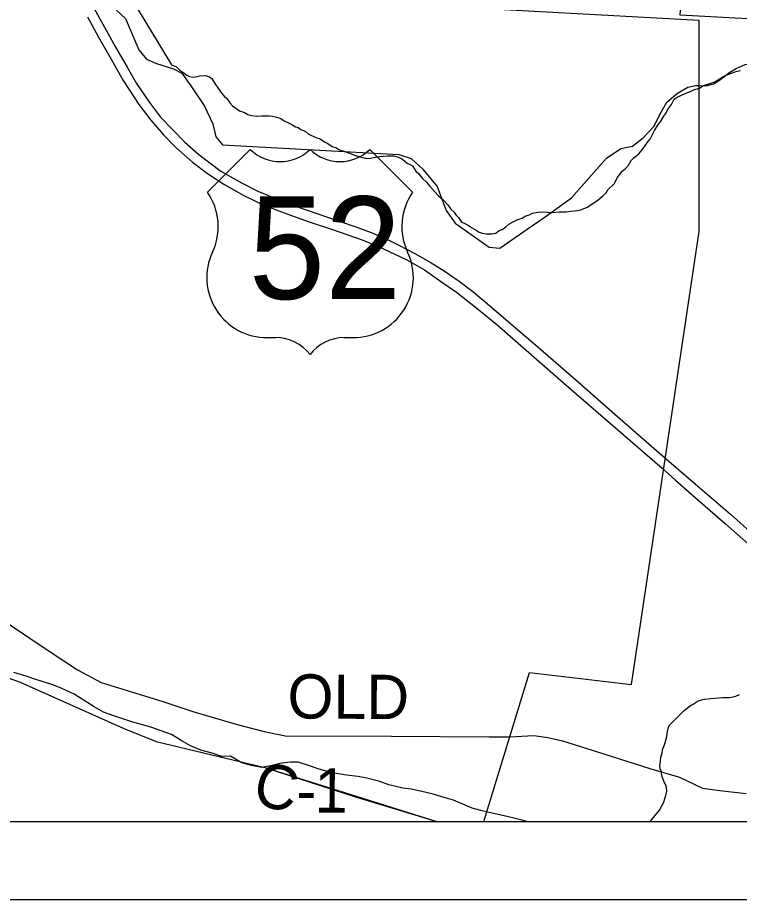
# Model space of a CAD drawing. Extents: x 0 to 45.4, y -2.2 to 22.
# Drawn here: x 5.063 to 5.991, y 14 to 15.133 of the extents above; entities that cross this region are included whole.
import ezdxf

# ---------------------------------------------------------------- set-up
doc = ezdxf.new("R2010")
doc.units = 0
for name, color, linetype in [('GM_X_Corporation', 7, 'Continuous'), ('GM_X_County_Road', 7, 'Continuous'), ('GM_X_County_Road_Text', 7, 'Continuous'), ('GM_X_Major_River', 7, 'Continuous'), ('GM_X_Minor_River', 7, 'Continuous'), ('GM_X_Township_Road', 7, 'Continuous'), ('GM_X_US_Location', 7, 'Continuous'), ('GM_X_US_Route', 7, 'Continuous'), ('GM_X_US_Shield', 7, 'Continuous'), ('SH_Data', 7, 'Continuous')]:
    doc.layers.add(name, color=color, linetype=linetype)

msp = doc.modelspace()

# ---------------------------------------------------------------- linework, layer by layer
at = {"layer": 'GM_X_Corporation'}
msp.add_lwpolyline([(5.9818, 16.1569), (7.1036, 16.0876), (7.0412, 15.0748), (5.9148, 15.1362)], close=True, dxfattribs=at)
for points in [[(3.8978, 15.2272), (3.9542, 15.1285), (4.0477, 14.9842), (4.1352, 14.8715), (4.2196, 14.8002), (4.388, 14.6465), (4.4527, 14.6021), (4.5557, 14.522), (4.7063, 14.4272), (4.7879, 14.3851), (4.9751, 14.3119), (5.0667, 14.2789), (5.1988, 14.2201), (5.2415, 14.2027), (5.3809, 14.1693), (5.499, 14.1314), (5.6021, 14.1), (7.0413, 14.1)], [(3.8978, 15.2272), (3.9542, 15.1285), (4.0477, 14.9842), (4.1352, 14.8715), (4.2196, 14.8002), (4.388, 14.6465), (4.4527, 14.6021), (4.5557, 14.522), (4.7063, 14.4272), (4.9751, 14.3119), (5.0667, 14.2789), (5.1988, 14.2201), (5.2415, 14.2027), (5.3809, 14.1693), (5.6023, 14.1), (5.6624, 14.1), (5.7213, 14.2916), (5.8523, 14.276), (5.9392, 14.8581), (5.9392, 15.1293), (5.6491, 15.1452)], [(4.8407, 15.1929), (4.8223, 15.0904), (4.8187, 15.0253), (4.8105, 14.8879), (4.809, 14.8625), (4.8057, 14.8075), (4.7972, 14.536), (4.7879, 14.3851), (4.9751, 14.3119), (5.0667, 14.2789), (5.1988, 14.2201), (5.2415, 14.2027), (5.3809, 14.1693), (5.499, 14.1314), (5.6021, 14.1), (7.0413, 14.1)]]:
    msp.add_lwpolyline(points, dxfattribs=at)
at = {"layer": 'GM_X_County_Road'}
for points in [[(5.0206, 14.3757), (5.0301, 14.3683), (5.1039, 14.3189), (5.1401, 14.2949), (5.1705, 14.2785), (5.2488, 14.2548), (5.2884, 14.2414), (5.3455, 14.2246), (5.38, 14.2156), (5.4034, 14.211)], [(5.4034, 14.211), (5.4073, 14.2103), (5.5438, 14.2096), (5.6692, 14.2087), (5.6961, 14.2087), (5.7268, 14.2106), (5.7446, 14.2078), (5.7638, 14.2036), (5.7867, 14.1965), (5.8195, 14.1862), (5.8757, 14.168), (5.9138, 14.1572), (5.9436, 14.1431), (5.9657, 14.1399), (5.9995, 14.1362)]]:
    msp.add_lwpolyline(points, dxfattribs=at)
at = {"layer": 'GM_X_Major_River'}
for points in [[(5.6474, 14.1171), (5.6236, 14.1274), (5.6115, 14.1308), (5.5975, 14.1353), (5.5812, 14.1391), (5.5691, 14.1414), (5.5585, 14.1429), (5.5404, 14.1471), (5.529, 14.1513), (5.512, 14.1558), (5.5011, 14.1577), (5.4859, 14.1596), (5.4731, 14.1619), (5.4629, 14.1638), (5.4496, 14.1676), (5.4383, 14.1717), (5.4239, 14.1763), (5.4141, 14.1763), (5.4005, 14.1748), (5.3887, 14.1717), (5.377, 14.1695), (5.3641, 14.1721), (5.3513, 14.1755), (5.337, 14.1838), (5.3256, 14.1835), (5.3135, 14.1877), (5.2987, 14.1918), (5.2855, 14.1975), (5.2734, 14.204), (5.2609, 14.2119), (5.2477, 14.2165), (5.236, 14.2207), (5.2227, 14.2245), (5.2114, 14.2279), (5.2012, 14.2313), (5.1845, 14.2366), (5.1739, 14.2404), (5.1615, 14.2476), (5.149, 14.2555), (5.1361, 14.2635), (5.1195, 14.2715), (5.1074, 14.276), (5.0976, 14.2791), (5.0843, 14.2832), (5.0745, 14.2866), (5.0586, 14.2916)], [(5.7179, 14.1), (5.7132, 14.1012), (5.6992, 14.1046), (5.683, 14.1088), (5.6731, 14.1107), (5.6588, 14.1141), (5.6474, 14.1171)]]:
    msp.add_lwpolyline(points, dxfattribs=at)
at = {"layer": 'GM_X_Minor_River'}
for points in [[(5.2111, 15.155), (5.2612, 15.0722), (5.2676, 15.0698), (5.2717, 15.0656), (5.2773, 15.0617), (5.2806, 15.059), (5.2844, 15.0574), (5.2889, 15.0566), (5.2939, 15.0572), (5.2977, 15.0583), (5.3045, 15.0586), (5.309, 15.0574)], [(5.8158, 14.9045), (5.8197, 14.9079), (5.822, 14.9116), (5.8301, 14.9195), (5.8344, 14.9274), (5.8403, 14.9356), (5.8445, 14.9393), (5.8484, 14.9435), (5.8519, 14.9495), (5.8553, 14.9528), (5.8619, 14.958), (5.8673, 14.9648), (5.8731, 14.9734), (5.8762, 14.9768), (5.879, 14.9821), (5.8817, 14.9881), (5.8864, 14.9956), (5.8895, 14.999), (5.8938, 15.0065), (5.8969, 15.0106), (5.8985, 15.0144), (5.9039, 15.0215), (5.907, 15.0283), (5.9109, 15.0309), (5.9212, 15.0357), (5.9281, 15.0382), (5.9319, 15.0401), (5.9395, 15.0422), (5.9449, 15.0459), (5.9544, 15.0488), (5.9593, 15.0506), (5.9628, 15.0525), (5.9708, 15.058), (5.9781, 15.0606), (5.988, 15.0642), (5.9925, 15.0649)], [(5.309, 15.0574), (5.3128, 15.0546), (5.3176, 15.047), (5.3205, 15.0427), (5.3257, 15.0354), (5.3287, 15.032), (5.3324, 15.0289), (5.3361, 15.0235), (5.3394, 15.0196), (5.3484, 15.0134), (5.3548, 15.011), (5.3593, 15.0087), (5.3642, 15.0071), (5.3699, 15.0066), (5.3771, 15.0068), (5.3809, 15.0068), (5.3866, 15.0067), (5.3907, 15.0062), (5.3949, 15.0054), (5.4016, 15.0034), (5.4058, 15.0003), (5.4114, 14.9979), (5.4159, 14.9956), (5.4204, 14.9928), (5.4238, 14.992), (5.4272, 14.9893), (5.4328, 14.9873), (5.4369, 14.9838), (5.4403, 14.9822), (5.4478, 14.9787), (5.4512, 14.9779), (5.4587, 14.9728), (5.4621, 14.9712), (5.4677, 14.9673), (5.473, 14.9657), (5.4771, 14.963), (5.4831, 14.9614), (5.4873, 14.9598), (5.491, 14.9586), (5.4963, 14.9562), (5.5034, 14.9542), (5.5068, 14.9534), (5.5117, 14.9522), (5.517, 14.9525), (5.525, 14.9542), (5.533, 14.9552), (5.5387, 14.9555), (5.5463, 14.9554), (5.5527, 14.9538), (5.5579, 14.951), (5.5639, 14.946), (5.571, 14.9424), (5.5751, 14.9359), (5.5784, 14.9328), (5.5836, 14.9263), (5.5889, 14.9216), (5.5926, 14.917), (5.5993, 14.9097), (5.6041, 14.9039), (5.6108, 14.8985), (5.6164, 14.8923), (5.6201, 14.8869), (5.6242, 14.883), (5.6264, 14.8796), (5.6305, 14.8757), (5.6338, 14.8703), (5.6372, 14.8688), (5.6417, 14.8668), (5.6465, 14.8633), (5.6525, 14.8598), (5.6567, 14.8574), (5.6604, 14.8562), (5.6657, 14.855), (5.6729, 14.8552), (5.6779, 14.8559), (5.6821, 14.8596), (5.6859, 14.8607), (5.6909, 14.8644), (5.6947, 14.8678), (5.6986, 14.8696), (5.7062, 14.8737), (5.7119, 14.8755), (5.7157, 14.8777), (5.7207, 14.8795), (5.7249, 14.8817), (5.7318, 14.8831), (5.7367, 14.8834), (5.7443, 14.8829), (5.7503, 14.8828), (5.7549, 14.8831), (5.7594, 14.8834), (5.7628, 14.8834), (5.7689, 14.8836), (5.7742, 14.8843), (5.7829, 14.8853), (5.7871, 14.886), (5.7909, 14.8878), (5.7959, 14.8896), (5.7993, 14.8919), (5.8089, 14.8985), (5.8158, 14.9045)], [(5.8762, 14.1), (5.8883, 14.1145), (5.8934, 14.1242), (5.8966, 14.1333), (5.8978, 14.139), (5.8968, 14.1462), (5.8943, 14.1508), (5.8925, 14.1554), (5.8914, 14.1588), (5.8907, 14.1638), (5.8893, 14.1676), (5.8889, 14.1714), (5.8894, 14.1775), (5.8899, 14.1828), (5.8911, 14.1866), (5.8927, 14.1934), (5.8951, 14.1998), (5.8976, 14.2092), (5.8984, 14.2157), (5.8996, 14.2195), (5.9009, 14.2236), (5.9124, 14.2348), (5.9201, 14.2427), (5.9282, 14.249), (5.9316, 14.2508), (5.9381, 14.2549), (5.9461, 14.2574), (5.9541, 14.258), (5.964, 14.259), (5.9693, 14.2593), (5.9776, 14.2595), (5.981, 14.2599), (5.9864, 14.2613), (5.9913, 14.2631)]]:
    msp.add_lwpolyline(points, dxfattribs=at)
at = {"layer": 'GM_X_Township_Road'}
for points in [[(5.1904, 15.1427), (5.2019, 15.1319), (5.2112, 15.1097), (5.2191, 15.0918), (5.2291, 15.0796), (5.242, 15.0739), (5.2635, 15.0674), (5.2743, 15.0617), (5.2858, 15.0452), (5.3037, 15.0194), (5.3144, 14.9965), (5.3181, 14.9799), (5.3268, 14.9695), (5.5532, 14.957), (5.5689, 14.952), (5.584, 14.9384), (5.6026, 14.9162), (5.6141, 14.8853), (5.6256, 14.8688), (5.6693, 14.8379), (5.6829, 14.8367), (5.7184, 14.861), (5.7414, 14.8769), (5.7751, 14.9014), (5.8202, 14.9526), (5.8386, 14.9649), (5.8534, 14.9679), (5.8672, 14.9787), (5.8811, 14.993), (5.8905, 15.0116), (5.8976, 15.0245), (5.9112, 15.0361), (5.9245, 15.0435), (5.9344, 15.046), (5.937, 15.0459)], [(5.937, 15.0459), (5.9388, 15.0458), (5.9483, 15.0454), (5.9577, 15.048), (5.9654, 15.0527), (5.9788, 15.0629), (5.9868, 15.0675), (5.9985, 15.0729), (6.0083, 15.074), (6.0225, 15.0762), (6.0358, 15.0791), (6.0516, 15.0793), (6.0671, 15.0795), (6.08, 15.08), (6.0904, 15.0783), (6.0993, 15.0749), (6.1077, 15.0675), (6.1142, 15.0611), (6.1204, 15.0573), (6.1326, 15.0571), (6.1801, 15.0639)]]:
    msp.add_lwpolyline(points, dxfattribs=at)
at = {"layer": 'GM_X_US_Route'}
for points in [[(5.1461, 15.1731), (5.1749, 15.1208), (5.1889, 15.0961), (5.2043, 15.0692), (5.2162, 15.0484), (5.233, 15.0238), (5.247, 15.0053), (5.2626, 14.9889), (5.2782, 14.9729), (5.2963, 14.957), (5.3244, 14.9358), (5.3509, 14.9206), (5.372, 14.9099), (5.4003, 14.8983), (5.4205, 14.8909), (5.4493, 14.881), (5.4764, 14.8714), (5.4993, 14.8637), (5.5197, 14.856), (5.5412, 14.8468), (5.5534, 14.8408), (5.574, 14.83), (5.5935, 14.819), (5.6116, 14.8076), (5.6309, 14.7945), (5.6485, 14.781), (5.6723, 14.7611), (5.7003, 14.7371), (5.7258, 14.7153), (5.7807, 14.6676), (5.8378, 14.6173), (5.888, 14.574), (5.9345, 14.5334), (5.9796, 14.4949), (6.0124, 14.4655)], [(5.1532, 15.134), (5.1673, 15.1078), (5.1836, 15.0797), (5.1991, 15.0524), (5.2192, 15.0215), (5.2345, 15.0014), (5.2509, 14.9825), (5.2662, 14.9665), (5.2881, 14.9473), (5.3072, 14.9326), (5.3282, 14.9191), (5.354, 14.9043), (5.3799, 14.8922), (5.4057, 14.8821), (5.4381, 14.8708), (5.468, 14.8609), (5.506, 14.8476), (5.5337, 14.8361), (5.5634, 14.8216), (5.5863, 14.8088), (5.6098, 14.7922), (5.6274, 14.7801), (5.6539, 14.7591), (5.6791, 14.7385), (5.7168, 14.7056), (5.7719, 14.6578), (5.8255, 14.6114), (5.8915, 14.5541), (5.9089, 14.5387)], [(5.9089, 14.5387), (5.937, 14.514), (5.9729, 14.4826), (6.0064, 14.4531), (6.0352, 14.4294), (6.0578, 14.4128), (6.0814, 14.3982), (6.105, 14.3868), (6.1338, 14.3766), (6.1611, 14.3701), (6.1846, 14.3664), (6.2056, 14.3653), (6.227, 14.3651), (6.2496, 14.3673), (6.2716, 14.3707), (6.2953, 14.3765), (6.3276, 14.3861)]]:
    msp.add_lwpolyline(points, dxfattribs=at)
at = {"layer": 'GM_X_US_Shield'}
for p, q in [((5.3623, 14.9637), (5.3073, 14.9087)), ((5.571, 14.9087), (5.5161, 14.9637)), ((5.3842, 14.722), (5.3952, 14.722)), ((5.4831, 14.722), (5.4941, 14.722))]:
    msp.add_line(p, q, dxfattribs=at)
for centre, radius, start, end in [((5.4007, 15.0029), 0.0549, 225.573, 314.427), ((5.4776, 15.0029), 0.0549, 225.573, 314.427), ((5.2443, 14.8646), 0.0769, 334.5471, 35.0009), ((5.634, 14.8646), 0.0769, 144.9991, 205.4529), ((5.3834, 14.7989), 0.0769, 154.8319, 270.6383), ((5.495, 14.7989), 0.0769, 269.3617, 25.1681), ((5.3952, 14.667), 0.0549, 36.8699, 90), ((5.4831, 14.667), 0.0549, 90, 143.1301)]:
    msp.add_arc(centre, radius, start, end, dxfattribs=at)
at = {"layer": 'SH_Data'}
for p, q in [((2.1, 14.1), (8.9, 14.1)), ((2, 14), (9, 14))]:
    msp.add_line(p, q, dxfattribs=at)

# ---------------------------------------------------------------- texts
at = {"layer": 'GM_X_County_Road_Text'}
for s, height, rotation, p in [('OLD', 0.05682, 359.6649, (5.4101, 14.2325)), ('C', 0.0568, 348.4496, (5.3637, 14.1222)), ('1', 0.0568, 359.7307, (5.445, 14.1116)), ('-', 0.0568, 359.8911, (5.4217, 14.1116))]:
    msp.add_text(s, height=height, rotation=rotation, dxfattribs=at).set_placement(p)
at = {"layer": 'GM_X_US_Location'}
for s in ['0', '/']:
    msp.add_text(s, height=0.000189, dxfattribs=at).set_placement((5.4391, 14.8363))
msp.add_text('52', height=0.000189, rotation=0, dxfattribs=at).set_placement((5.4, 14.7971))
at = {"layer": 'GM_X_US_Shield'}
msp.add_text('52', height=0.13184, dxfattribs=at).set_placement((5.3604, 14.7714))

doc.saveas('drawing.dxf')
